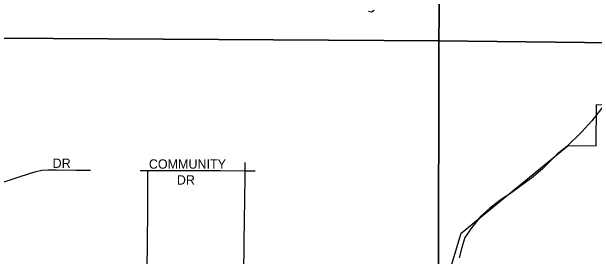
# Model space of a CAD drawing. Extents: x -97 to 34, y -21 to 22.
# Drawn here: x 6.163 to 6.753, y 18.248 to 18.496 of the extents above; entities that cross this region are included whole.
import ezdxf

# ---------------------------------------------------------------- set-up
doc = ezdxf.new("R2010")
doc.units = 0
for name, color, linetype in [('GM_X_City_Street', 7, 'Continuous'), ('GM_X_City_Street_Text', 7, 'Continuous'), ('GM_X_Corporation', 7, 'Continuous'), ('GM_X_Minor_River', 7, 'Continuous'), ('GM_X_Section', 7, 'Continuous')]:
    doc.layers.add(name, color=color, linetype=linetype)

msp = doc.modelspace()

# ---------------------------------------------------------------- linework, layer by layer
at = {"layer": 'GM_X_City_Street'}
for points in [[(6.52985, 18.49691), (6.52723, 18.4954), (6.52428, 18.4959)], [(6.39924, 18.33439), (6.39921, 18.34292)], [(6.07543, 18.29742), (6.08574, 18.30072), (6.09871, 18.30487), (6.12078, 18.31224), (6.14327, 18.3194), (6.15715, 18.32376), (6.16833, 18.3276), (6.18183, 18.33187), (6.18768, 18.33362), (6.19352, 18.33496), (6.1997, 18.33529), (6.20837, 18.33529), (6.2279, 18.33513), (6.24275, 18.33496)], [(6.29313, 18.33464), (6.30081, 18.33467)], [(6.30017, 18.2352), (6.30033, 18.26123), (6.30065, 18.29444), (6.30081, 18.31829), (6.30081, 18.33097), (6.30081, 18.33467)], [(6.30081, 18.33467), (6.34883, 18.33486), (6.37393, 18.33469), (6.39903, 18.33439), (6.39924, 18.33439)], [(6.39658, 18.06444), (6.39665, 18.07304), (6.39665, 18.10156), (6.39713, 18.14913), (6.39795, 18.1944), (6.39811, 18.22755), (6.39834, 18.26247), (6.39927, 18.32746), (6.39924, 18.33439)], [(6.39924, 18.33439), (6.40943, 18.33434)]]:
    msp.add_lwpolyline(points, dxfattribs=at)
at = {"layer": 'GM_X_Corporation'}
msp.add_lwpolyline([(6.57589, 18.13086), (6.61803, 18.27128), (6.72646, 18.36016), (6.75487, 18.35989), (6.75518, 18.40155), (6.79896, 18.40115), (6.78973, 18.14939)], dxfattribs=at)
at = {"layer": 'GM_X_Minor_River'}
msp.add_lwpolyline([(6.76384, 18.40244), (6.75034, 18.38519), (6.73995, 18.37358), (6.72497, 18.35863), (6.7154, 18.35118), (6.70043, 18.3366), (6.68931, 18.3269), (6.67859, 18.31908), (6.66826, 18.31127), (6.6587, 18.30533), (6.64722, 18.29639), (6.63763, 18.28819), (6.62877, 18.27694), (6.62181, 18.2668), (6.61864, 18.25661), (6.61622, 18.24602)], dxfattribs=at)
at = {"layer": 'GM_X_Section'}
for points in [[(5.59615, 19.47364), (6.60805, 19.46219), (6.59547, 18.46625), (5.59082, 18.47236)], [(6.60805, 19.46219), (7.61097, 19.41205), (7.59861, 18.45475), (6.59547, 18.46625)], [(5.59082, 18.47236), (6.59547, 18.46625), (6.59419, 17.46305), (5.58508, 17.4654)], [(6.59547, 18.46625), (7.59861, 18.45475), (7.59283, 17.45801), (6.59419, 17.46305)]]:
    msp.add_lwpolyline(points, close=True, dxfattribs=at)

# ---------------------------------------------------------------- texts
at = {"layer": 'GM_X_City_Street_Text'}
for s, p in [('DR', (6.20433, 18.33739)), ('COMMUNITY', (6.30182, 18.33656)), ('DR', (6.33016, 18.32045))]:
    msp.add_text(s, height=0.00947, rotation=0.00001, dxfattribs=at).set_placement(p)

doc.saveas('drawing.dxf')
